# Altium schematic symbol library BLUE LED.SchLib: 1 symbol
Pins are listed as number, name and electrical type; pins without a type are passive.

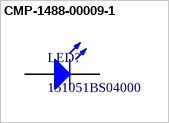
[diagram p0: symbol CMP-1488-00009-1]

## CMP-1488-00009-1
designator LED?, comment 151051BS04000
THT LED round mono-color color lens, WL-TMRW, Blue; Manufacturer: Wuerth Elektronik
footprint Type 5mm (THT, LED-5mm, 2pin- Body 5.8mm)
pins: 1 K, 2 A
